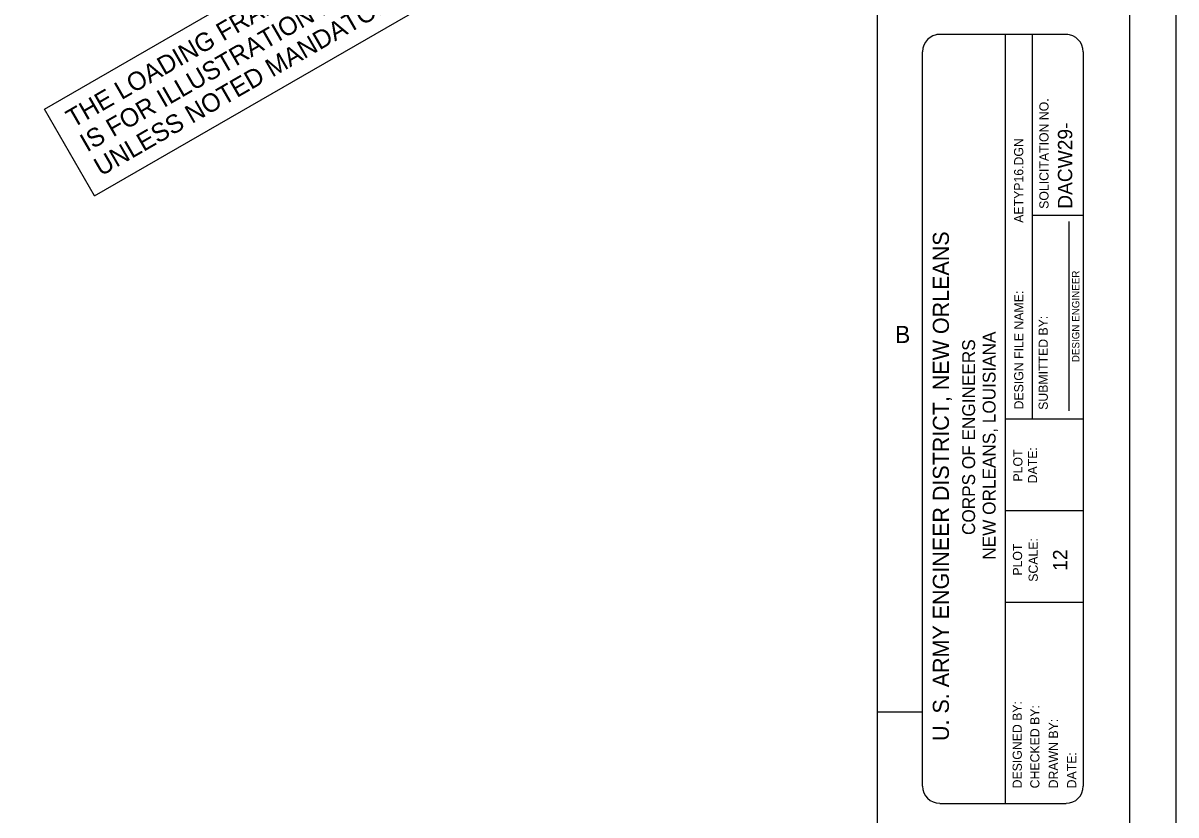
# Model space of a CAD drawing. Extents: x 22369.6 to 22413.6, y 22369.6 to 22403.6.
# Drawn here: x 22401.07 to 22413.62, y 22377.25 to 22385.88 of the extents above; entities that cross this region are included whole.
import ezdxf

# ---------------------------------------------------------------- set-up
doc = ezdxf.new("R2010")
doc.units = 0
for name, color, linetype in [('Level 1', 7, 'Continuous'), ('Level 10', 7, 'Continuous'), ('Level 2', 7, 'Continuous'), ('Level 7', 7, 'Continuous'), ('Level 9', 7, 'Continuous')]:
    doc.layers.add(name, color=color, linetype=linetype)

msp = doc.modelspace()

# ---------------------------------------------------------------- linework, layer by layer
at = {"layer": 'Level 1'}
for p, q in [((22412.446, 22385.749), (22411.018, 22385.749)), ((22411.762, 22385.749), (22411.762, 22377.373))]:
    msp.add_line(p, q, dxfattribs=at)
msp.add_lwpolyline([(22369.621, 22403.629), (22413.622, 22403.629), (22413.622, 22369.621), (22369.621, 22369.621)], close=True, dxfattribs=at)
for points in [[(22412.426, 22385.749), (22411.049, 22385.749)], [(22410.862, 22377.561), (22410.862, 22385.562)], [(22412.614, 22377.561), (22412.614, 22385.562)], [(22411.049, 22377.373), (22412.426, 22377.373)]]:
    msp.add_lwpolyline(points, dxfattribs=at)
for centre, radius, start, end in [((22411.049, 22385.562), 0.188, 90, 180), ((22412.426, 22385.562), 0.187, 0, 90), ((22411.049, 22377.561), 0.187, 180, 270), ((22412.426, 22377.561), 0.187, 270, 0)]:
    msp.add_arc(centre, radius, start, end, dxfattribs=at)
at = {"layer": 'Level 10'}
for p, q in [((22401.298, 22384.937), (22406.796, 22388.112)), ((22401.844, 22383.991), (22407.343, 22387.165)), ((22401.844, 22383.991), (22401.298, 22384.937)), ((22410.37, 22378.369), (22410.862, 22378.369))]:
    msp.add_line(p, q, dxfattribs=at)
at = {"layer": 'Level 2'}
for p, q in [((22412.057, 22385.749), (22412.057, 22381.561)), ((22412.614, 22383.778), (22412.057, 22383.778)), ((22412.458, 22381.652), (22412.458, 22383.713)), ((22412.614, 22381.561), (22411.762, 22381.561)), ((22412.614, 22380.561), (22411.762, 22380.561)), ((22412.614, 22379.561), (22411.762, 22379.561))]:
    msp.add_line(p, q, dxfattribs=at)
at = {"layer": 'Level 9'}
msp.add_line((22413.118, 22370.125), (22413.118, 22403.125), dxfattribs=at)
msp.add_lwpolyline([(22410.37, 22370.125), (22410.37, 22403.125)], dxfattribs=at)

# ---------------------------------------------------------------- texts
at = {"layer": 'Level 1'}
for s, height, p in [('SOLICITATION NO.', 0.10001, (22412.234, 22383.851)), ('AETYP16.DGN', 0.10001, (22411.959, 22383.699)), ('U. S. ARMY ENGINEER DISTRICT, NEW ORLEANS', 0.175, (22411.149, 22378.053)), ('DESIGN ENGINEER', 0.07999, (22412.57, 22382.18)), ('DESIGN FILE NAME:', 0.10001, (22411.96, 22381.666)), ('SUBMITTED BY:', 0.10001, (22412.226, 22381.661)), ('PLOT', 0.1, (22411.95, 22380.88)), ('DATE:', 0.1, (22412.11, 22380.86)), ('PLOT', 0.1, (22411.946, 22379.855)), ('SCALE:', 0.1, (22412.117, 22379.788)), ('DESIGNED BY:', 0.10001, (22411.943, 22377.537)), ('CHECKED BY:', 0.10001, (22412.135, 22377.537)), ('DRAWN BY:', 0.1, (22412.337, 22377.537)), ('DATE:', 0.1, (22412.536, 22377.537))]:
    msp.add_text(s, height=height, rotation=90, dxfattribs=at).set_placement(p)
msp.add_text('B', height=0.187, dxfattribs=at).set_placement((22410.562, 22382.389))
at = {"layer": 'Level 7'}
for s, height, rotation, p in [('THE LOADING FRAME AND TEST APPARATUS', 0.2, 30.0029, (22401.61, 22384.729)), ('IS FOR ILLUSTRATION PURPOSES ONLY,', 0.2, 30.0029, (22401.762, 22384.465)), ('UNLESS NOTED MANDATORY.', 0.2, 30.0029, (22401.914, 22384.202)), ('DACW29-', 0.156, 90, (22412.492, 22383.852)), ('NEW ORLEANS, LOUISIANA', 0.14, 90, (22411.657, 22380.028)), ('CORPS OF ENGINEERS', 0.14, 90, (22411.434, 22380.297)), ('12', 0.156, 90, (22412.439, 22379.908))]:
    msp.add_text(s, height=height, rotation=rotation, dxfattribs=at).set_placement(p)

doc.saveas('drawing.dxf')
